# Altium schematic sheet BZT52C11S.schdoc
size 127 x 101 mm
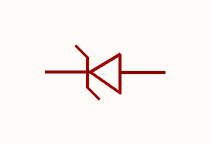
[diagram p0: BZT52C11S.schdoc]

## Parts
ZD?  bzt52c11s_c22615  [SOD-323_L1.8-W1.3-LS2.5-RD]  (value not drawn)

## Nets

Not connected (* = marked no-connect by the designer): ZD? 1(K) 2(A)

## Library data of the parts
ZD? = bzt52c11s_c22615: 二极管配置:1个独立式;稳压值(标称值):11V;稳压值(范围):10.4V~11.6V;耗散功率(Pd):200mW;; Manufacturer: CJ(江苏长电/长晶); AddInBom: yes; ModelId: db63db13d9e342eb939127d413d6200b; ModelTransform: 104.3305,51.181,0,0,0,0,0,-0.004,0; Diode Configuration: 1个独立式; Zener Voltage(Nom): 11V; Reverse Leakage Current (Ir): 100nA; Pd - Power Dissipation: 200mW; Impedance(Zzt): 20Ω; Impedance(Zzk): 150Ω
